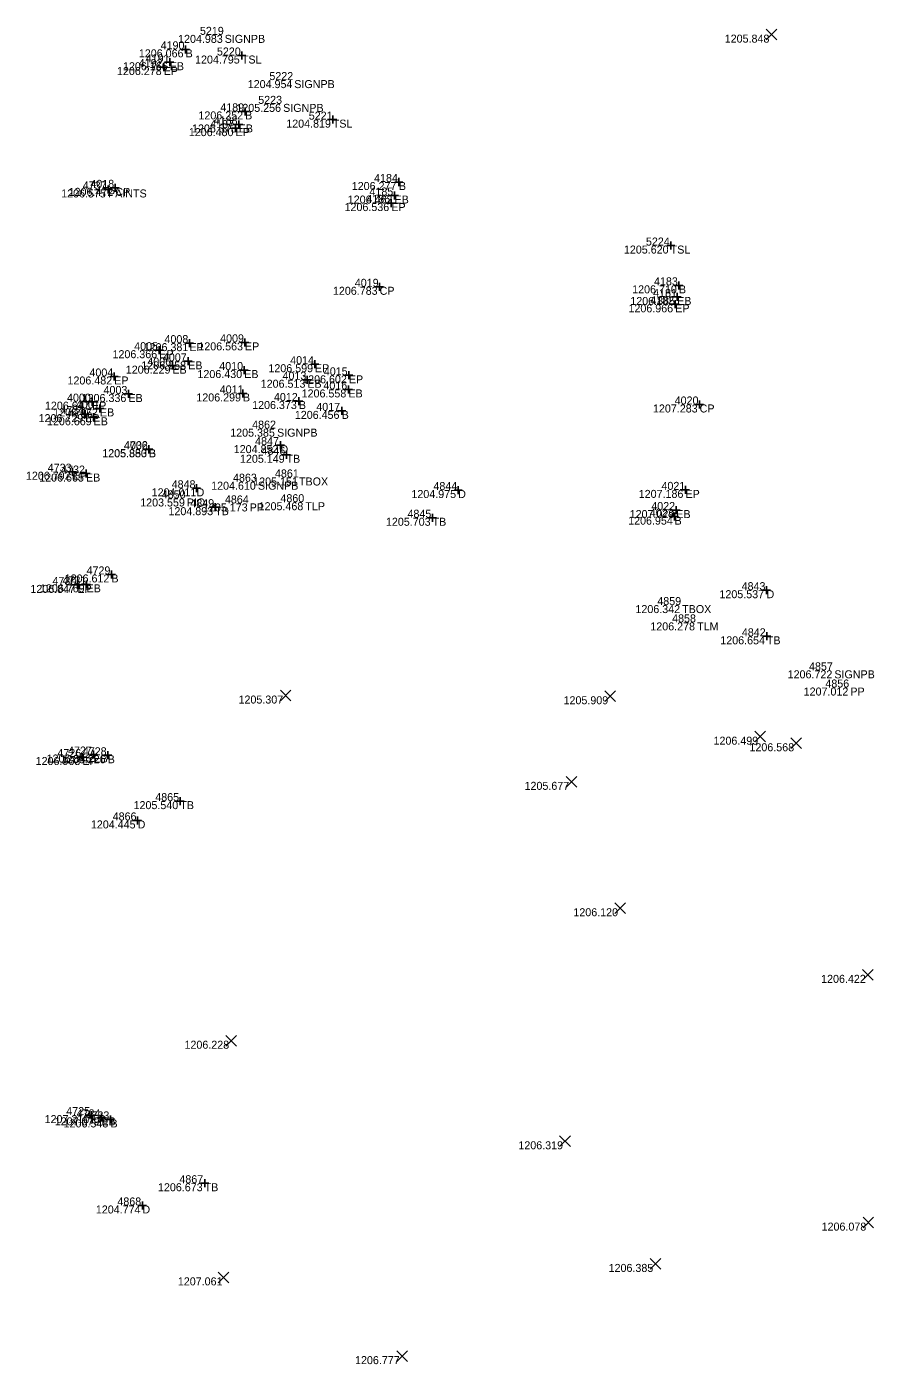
# Model space of a CAD drawing. Extents: x 2044997 to 2050342, y 455233 to 458054.
# Drawn here: x 2047638.8 to 2047744.6, y 456841.8 to 457008.9 of the extents above; entities that cross this region are included whole.
import ezdxf

# ---------------------------------------------------------------- set-up
doc = ezdxf.new("R2010")
doc.units = 0
for name, color, linetype in [('SV_X_Random_Point', 7, 'Continuous'), ('SV_X_Shot_Marker', 7, 'Continuous'), ('SV_X_Text_Comment', 7, 'Continuous'), ('SV_X_Text_Elevation', 7, 'Continuous'), ('SV_X_Text_Name', 7, 'Continuous')]:
    doc.layers.add(name, color=color, linetype=linetype)

msp = doc.modelspace()

# ---------------------------------------------------------------- linework, layer by layer
at = {"layer": 'SV_X_Random_Point'}
for p, q in [((2047731.12, 457007.26), (2047732.46, 457008.6)), ((2047731.12, 457008.6), (2047732.46, 457007.26)), ((2047670.46, 456924.7), (2047671.79, 456926.04)), ((2047670.46, 456926.04), (2047671.79, 456924.7)), ((2047710.98, 456924.61), (2047712.32, 456925.95)), ((2047710.98, 456925.95), (2047712.32, 456924.61)), ((2047729.71, 456919.57), (2047731.04, 456920.9)), ((2047729.71, 456920.9), (2047731.04, 456919.57)), ((2047734.22, 456918.74), (2047735.56, 456920.08)), ((2047734.22, 456920.08), (2047735.56, 456918.74)), ((2047706.17, 456913.92), (2047707.51, 456915.25)), ((2047706.17, 456915.25), (2047707.51, 456913.92)), ((2047712.23, 456898.14), (2047713.56, 456899.47)), ((2047712.23, 456899.47), (2047713.56, 456898.14)), ((2047743.16, 456889.81), (2047744.5, 456891.15)), ((2047743.16, 456891.15), (2047744.5, 456889.81)), ((2047663.66, 456881.58), (2047664.99, 456882.92)), ((2047663.66, 456882.92), (2047664.99, 456881.58)), ((2047705.34, 456869.02), (2047706.68, 456870.35)), ((2047705.34, 456870.35), (2047706.68, 456869.02)), ((2047743.23, 456858.86), (2047744.56, 456860.2)), ((2047743.23, 456860.2), (2047744.56, 456858.86)), ((2047716.64, 456853.71), (2047717.98, 456855.04)), ((2047716.64, 456855.04), (2047717.98, 456853.71)), ((2047662.71, 456852.02), (2047664.04, 456853.36)), ((2047662.71, 456853.36), (2047664.04, 456852.02)), ((2047685, 456842.18), (2047686.33, 456843.52)), ((2047685, 456843.52), (2047686.33, 456842.18))]:
    msp.add_line(p, q, dxfattribs=at)
at = {"layer": 'SV_X_Shot_Marker'}
for p, q in [((2047658.13, 457006.09), (2047659.13, 457006.09)), ((2047658.63, 457006.59), (2047658.63, 457005.59)), ((2047658.63, 457006.09), (2047658.63, 457006.09)), ((2047665.16, 457005.32), (2047666.16, 457005.32)), ((2047665.66, 457005.82), (2047665.66, 457004.82)), ((2047665.66, 457005.32), (2047665.66, 457005.32)), ((2047655.4, 457003.88), (2047656.4, 457003.88)), ((2047655.9, 457004.38), (2047655.9, 457003.38)), ((2047655.9, 457003.88), (2047655.9, 457003.88)), ((2047656.15, 457004.48), (2047657.15, 457004.48)), ((2047656.65, 457004.98), (2047656.65, 457003.98)), ((2047656.65, 457004.48), (2047656.65, 457004.48)), ((2047666.06, 456998.84), (2047666.06, 456997.84)), ((2047665.26, 456997.21), (2047665.26, 456996.21)), ((2047665.56, 456998.34), (2047666.56, 456998.34)), ((2047666.06, 456998.34), (2047666.06, 456998.34)), ((2047676.51, 456997.31), (2047677.51, 456997.31)), ((2047677.01, 456997.81), (2047677.01, 456996.81)), ((2047677.01, 456997.31), (2047677.01, 456997.31)), ((2047664.37, 456996.25), (2047665.37, 456996.25)), ((2047664.76, 456996.71), (2047665.76, 456996.71)), ((2047664.87, 456996.75), (2047664.87, 456995.75)), ((2047664.87, 456996.25), (2047664.87, 456996.25)), ((2047665.26, 456996.71), (2047665.26, 456996.71)), ((2047648.94, 456989.09), (2047648.94, 456988.09)), ((2047649.35, 456988.79), (2047650.35, 456988.79)), ((2047649.85, 456989.29), (2047649.85, 456988.29)), ((2047649.85, 456988.79), (2047649.85, 456988.79)), ((2047684.76, 456989.52), (2047685.76, 456989.52)), ((2047685.26, 456990.02), (2047685.26, 456989.02)), ((2047685.26, 456989.52), (2047685.26, 456989.52)), ((2047648.44, 456988.59), (2047649.44, 456988.59)), ((2047648.94, 456988.59), (2047648.94, 456988.59)), ((2047684.22, 456987.83), (2047685.22, 456987.83)), ((2047684.32, 456987.39), (2047684.32, 456986.39)), ((2047684.72, 456988.33), (2047684.72, 456987.33)), ((2047684.72, 456987.83), (2047684.72, 456987.83)), ((2047683.82, 456986.89), (2047684.82, 456986.89)), ((2047684.32, 456986.89), (2047684.32, 456986.89)), ((2047719.21, 456982.08), (2047719.21, 456981.08)), ((2047718.71, 456981.58), (2047719.71, 456981.58)), ((2047719.21, 456981.58), (2047719.21, 456981.58)), ((2047682.86, 456976.93), (2047682.86, 456975.93)), ((2047720.24, 456977.11), (2047720.24, 456976.11)), ((2047682.36, 456976.43), (2047683.36, 456976.43)), ((2047682.86, 456976.43), (2047682.86, 456976.43)), ((2047719.74, 456976.61), (2047720.74, 456976.61)), ((2047720.02, 456975.66), (2047720.02, 456974.66)), ((2047720.24, 456976.61), (2047720.24, 456976.61)), ((2047719.28, 456974.24), (2047720.28, 456974.24)), ((2047719.52, 456975.16), (2047720.52, 456975.16)), ((2047719.78, 456974.74), (2047719.78, 456973.74)), ((2047719.78, 456974.24), (2047719.78, 456974.24)), ((2047720.02, 456975.16), (2047720.02, 456975.16)), ((2047655.34, 456969.01), (2047655.34, 456968.01)), ((2047658.61, 456969.39), (2047659.61, 456969.39)), ((2047659.11, 456969.89), (2047659.11, 456968.89)), ((2047659.11, 456969.39), (2047659.11, 456969.39)), ((2047665.54, 456969.49), (2047666.54, 456969.49)), ((2047666.04, 456969.99), (2047666.04, 456968.99)), ((2047666.04, 456969.49), (2047666.04, 456969.49)), ((2047654.84, 456968.51), (2047655.84, 456968.51)), ((2047655.34, 456968.51), (2047655.34, 456968.51)), ((2047656.98, 456967.08), (2047656.98, 456966.08)), ((2047658.45, 456967.12), (2047659.45, 456967.12)), ((2047658.95, 456967.62), (2047658.95, 456966.62)), ((2047658.95, 456967.12), (2047658.95, 456967.12)), ((2047674.78, 456967.26), (2047674.78, 456966.26)), ((2047649.21, 456965.23), (2047650.21, 456965.23)), ((2047649.71, 456965.73), (2047649.71, 456964.73)), ((2047649.71, 456965.23), (2047649.71, 456965.23)), ((2047656.48, 456966.58), (2047657.48, 456966.58)), ((2047656.98, 456966.58), (2047656.98, 456966.58)), ((2047665.45, 456966.03), (2047666.45, 456966.03)), ((2047665.95, 456966.53), (2047665.95, 456965.53)), ((2047665.95, 456966.03), (2047665.95, 456966.03)), ((2047673.83, 456965.32), (2047673.83, 456964.32)), ((2047674.28, 456966.76), (2047675.28, 456966.76)), ((2047674.78, 456966.76), (2047674.78, 456966.76)), ((2047678.52, 456965.37), (2047679.52, 456965.37)), ((2047679.02, 456965.87), (2047679.02, 456964.87)), ((2047679.02, 456965.37), (2047679.02, 456965.37)), ((2047665.79, 456963.61), (2047665.79, 456962.61)), ((2047673.33, 456964.82), (2047674.33, 456964.82)), ((2047673.83, 456964.82), (2047673.83, 456964.82)), ((2047678.46, 456963.61), (2047679.46, 456963.61)), ((2047678.96, 456964.11), (2047678.96, 456963.11)), ((2047678.96, 456963.61), (2047678.96, 456963.61)), ((2047646.44, 456962.08), (2047647.44, 456962.08)), ((2047646.94, 456962.58), (2047646.94, 456961.58)), ((2047646.94, 456962.08), (2047646.94, 456962.08)), ((2047650.99, 456963.04), (2047651.99, 456963.04)), ((2047651.49, 456963.54), (2047651.49, 456962.54)), ((2047651.49, 456963.04), (2047651.49, 456963.04)), ((2047665.29, 456963.11), (2047666.29, 456963.11)), ((2047665.79, 456963.11), (2047665.79, 456963.11)), ((2047672.27, 456962.16), (2047673.27, 456962.16)), ((2047672.77, 456962.66), (2047672.77, 456961.66)), ((2047672.77, 456962.16), (2047672.77, 456962.16)), ((2047722.83, 456962.23), (2047722.83, 456961.23)), ((2047645.59, 456960.52), (2047646.59, 456960.52)), ((2047646.09, 456961.02), (2047646.09, 456960.02)), ((2047646.09, 456960.52), (2047646.09, 456960.52)), ((2047647.14, 456960.63), (2047647.14, 456959.63)), ((2047647.43, 456961.24), (2047648.43, 456961.24)), ((2047647.93, 456961.74), (2047647.93, 456960.74)), ((2047647.93, 456961.24), (2047647.93, 456961.24)), ((2047677.62, 456960.93), (2047678.62, 456960.93)), ((2047678.12, 456961.43), (2047678.12, 456960.43)), ((2047678.12, 456960.93), (2047678.12, 456960.93)), ((2047722.33, 456961.73), (2047723.33, 456961.73)), ((2047722.83, 456961.73), (2047722.83, 456961.73)), ((2047646.64, 456960.13), (2047647.64, 456960.13)), ((2047647.14, 456960.13), (2047647.14, 456960.13)), ((2047670.47, 456957.15), (2047670.47, 456956.15)), ((2047653.54, 456956.12), (2047654.54, 456956.12)), ((2047653.55, 456956.15), (2047654.55, 456956.15)), ((2047654.04, 456956.62), (2047654.04, 456955.62)), ((2047654.04, 456956.12), (2047654.04, 456956.12)), ((2047654.05, 456956.65), (2047654.05, 456955.65)), ((2047654.05, 456956.15), (2047654.05, 456956.15)), ((2047669.97, 456956.65), (2047670.97, 456956.65)), ((2047670.47, 456956.65), (2047670.47, 456956.65)), ((2047670.73, 456955.45), (2047671.73, 456955.45)), ((2047671.23, 456955.95), (2047671.23, 456954.95)), ((2047671.23, 456955.45), (2047671.23, 456955.45)), ((2047644.52, 456953.83), (2047644.52, 456952.83)), ((2047646.19, 456953.6), (2047646.19, 456952.6)), ((2047644.02, 456953.33), (2047645.02, 456953.33)), ((2047644.52, 456953.33), (2047644.52, 456953.33)), ((2047645.69, 456953.1), (2047646.69, 456953.1)), ((2047646.19, 456953.1), (2047646.19, 456953.1)), ((2047659.5, 456951.26), (2047660.5, 456951.26)), ((2047660, 456951.76), (2047660, 456950.76)), ((2047660, 456951.26), (2047660, 456951.26)), ((2047692.17, 456951.04), (2047693.17, 456951.04)), ((2047692.67, 456951.54), (2047692.67, 456950.54)), ((2047692.67, 456951.04), (2047692.67, 456951.04)), ((2047720.56, 456951.06), (2047721.56, 456951.06)), ((2047721.06, 456951.56), (2047721.06, 456950.56)), ((2047721.06, 456951.06), (2047721.06, 456951.06)), ((2047661.82, 456948.9), (2047662.82, 456948.9)), ((2047662.32, 456949.4), (2047662.32, 456948.4)), ((2047662.32, 456948.9), (2047662.32, 456948.9)), ((2047719.41, 456948.54), (2047720.41, 456948.54)), ((2047719.91, 456949.04), (2047719.91, 456948.04)), ((2047719.91, 456948.54), (2047719.91, 456948.54)), ((2047688.97, 456947.58), (2047689.97, 456947.58)), ((2047689.47, 456948.08), (2047689.47, 456947.08)), ((2047689.47, 456947.58), (2047689.47, 456947.58)), ((2047719.2, 456947.72), (2047720.2, 456947.72)), ((2047719.7, 456948.22), (2047719.7, 456947.22)), ((2047719.7, 456947.72), (2047719.7, 456947.72)), ((2047648.86, 456940.5), (2047649.86, 456940.5)), ((2047649.36, 456941), (2047649.36, 456940)), ((2047649.36, 456940.5), (2047649.36, 456940.5)), ((2047644.62, 456939.19), (2047645.62, 456939.19)), ((2047645.12, 456939.69), (2047645.12, 456938.69)), ((2047645.12, 456939.19), (2047645.12, 456939.19)), ((2047645.76, 456939.26), (2047646.76, 456939.26)), ((2047646.26, 456939.76), (2047646.26, 456938.76)), ((2047646.26, 456939.26), (2047646.26, 456939.26)), ((2047730.68, 456938.53), (2047731.68, 456938.53)), ((2047731.18, 456939.03), (2047731.18, 456938.03)), ((2047731.18, 456938.53), (2047731.18, 456938.53)), ((2047730.72, 456932.77), (2047731.72, 456932.77)), ((2047731.22, 456933.27), (2047731.22, 456932.27)), ((2047731.22, 456932.77), (2047731.22, 456932.77)), ((2047647.12, 456918.5), (2047647.12, 456917.5)), ((2047645.23, 456917.69), (2047646.23, 456917.69)), ((2047645.73, 456918.19), (2047645.73, 456917.19)), ((2047645.73, 456917.69), (2047645.73, 456917.69)), ((2047646.62, 456918), (2047647.62, 456918)), ((2047647.12, 456918), (2047647.12, 456918)), ((2047648.4, 456917.91), (2047649.4, 456917.91)), ((2047648.9, 456918.41), (2047648.9, 456917.41)), ((2047648.9, 456917.91), (2047648.9, 456917.91)), ((2047657.47, 456912.18), (2047658.47, 456912.18)), ((2047657.97, 456912.68), (2047657.97, 456911.68)), ((2047657.97, 456912.18), (2047657.97, 456912.18)), ((2047652.64, 456910.27), (2047652.64, 456909.27)), ((2047652.14, 456909.77), (2047653.14, 456909.77)), ((2047652.64, 456909.77), (2047652.64, 456909.77)), ((2047646.85, 456873.46), (2047646.85, 456872.46)), ((2047646.35, 456872.96), (2047647.35, 456872.96)), ((2047646.85, 456872.96), (2047646.85, 456872.96)), ((2047647.61, 456872.68), (2047648.61, 456872.68)), ((2047648.11, 456873.18), (2047648.11, 456872.18)), ((2047648.11, 456872.68), (2047648.11, 456872.68)), ((2047648.74, 456872.42), (2047649.74, 456872.42)), ((2047649.24, 456872.92), (2047649.24, 456871.92)), ((2047649.24, 456872.42), (2047649.24, 456872.42)), ((2047660.51, 456864.45), (2047661.51, 456864.45)), ((2047661.01, 456864.95), (2047661.01, 456863.95)), ((2047661.01, 456864.45), (2047661.01, 456864.45)), ((2047652.73, 456861.67), (2047653.73, 456861.67)), ((2047653.23, 456862.17), (2047653.23, 456861.17)), ((2047653.23, 456861.67), (2047653.23, 456861.67))]:
    msp.add_line(p, q, dxfattribs=at)

# ---------------------------------------------------------------- texts
at = {"layer": 'SV_X_Text_Comment'}
for s, p in [('SIGNPB', (2047663.51, 457006.9)), ('B', (2047658.63, 457005.09)), ('TSL', (2047665.66, 457004.32)), ('EP', (2047655.9, 457002.88)), ('EB', (2047656.65, 457003.48)), ('SIGNPB', (2047672.2, 457001.25)), ('SIGNPB', (2047670.81, 456998.28)), ('B', (2047666.06, 456997.34)), ('TSL', (2047677.01, 456996.31)), ('EP', (2047664.87, 456995.25)), ('EB', (2047665.26, 456995.71)), ('CP', (2047649.85, 456987.79)), ('B', (2047685.26, 456988.52)), ('PAINTS', (2047648.94, 456987.59)), ('EB', (2047684.72, 456986.83)), ('EP', (2047684.32, 456985.89)), ('TSL', (2047719.21, 456980.58)), ('CP', (2047682.86, 456975.43)), ('B', (2047720.24, 456975.61)), ('EP', (2047719.78, 456973.24)), ('EB', (2047720.02, 456974.16)), ('EP', (2047659.11, 456968.39)), ('EP', (2047666.04, 456968.49)), ('EP', (2047655.34, 456967.51)), ('EB', (2047658.95, 456966.12)), ('EP', (2047649.71, 456964.23)), ('EB', (2047656.98, 456965.58)), ('EB', (2047665.95, 456965.03)), ('EP', (2047674.78, 456965.76)), ('EP', (2047679.02, 456964.37)), ('EB', (2047673.83, 456963.82)), ('EB', (2047678.96, 456962.61)), ('EP', (2047646.94, 456961.08)), ('EB', (2047651.49, 456962.04)), ('B', (2047665.79, 456962.11)), ('B', (2047672.77, 456961.16)), ('EP', (2047646.09, 456959.52)), ('EB', (2047647.93, 456960.24)), ('B', (2047678.12, 456959.93)), ('CP', (2047722.83, 456960.73)), ('EB', (2047647.14, 456959.13)), ('SIGNPB', (2047670.05, 456957.71)), ('B', (2047654.04, 456955.12)), ('B', (2047654.05, 456955.15)), ('D', (2047670.47, 456955.65)), ('TB', (2047671.23, 456954.45)), ('EP', (2047644.52, 456952.33)), ('EB', (2047646.19, 456952.1)), ('SIGNPB', (2047667.66, 456951.08)), ('TBOX', (2047672.79, 456951.61)), ('D', (2047660, 456950.26)), ('D', (2047692.67, 456950.04)), ('EP', (2047721.06, 456950.06)), ('PIO', (2047658.77, 456948.99)), ('TB', (2047662.32, 456947.9)), ('PP', (2047666.63, 456948.37)), ('TLP', (2047673.59, 456948.52)), ('EB', (2047719.91, 456947.54)), ('TB', (2047689.47, 456946.58)), ('B', (2047719.7, 456946.72)), ('B', (2047649.36, 456939.5)), ('EP', (2047645.12, 456938.19)), ('EB', (2047646.26, 456938.26)), ('D', (2047731.18, 456937.53)), ('TBOX', (2047720.64, 456935.67)), ('TLM', (2047722.51, 456933.51)), ('TB', (2047731.22, 456931.77)), ('SIGNPB', (2047739.65, 456927.52)), ('PP', (2047741.65, 456925.37)), ('EP', (2047645.73, 456916.69)), ('EB', (2047647.12, 456917)), ('B', (2047648.9, 456916.91)), ('TB', (2047657.97, 456911.18)), ('D', (2047652.64, 456908.77)), ('EP', (2047646.85, 456871.96)), ('EB', (2047648.11, 456871.68)), ('B', (2047649.24, 456871.42)), ('TB', (2047661.01, 456863.45)), ('D', (2047653.23, 456860.67))]:
    msp.add_text(s, height=1, dxfattribs=at).set_placement(p)
at = {"layer": 'SV_X_Text_Elevation'}
for s, p in [('1204.983', (2047657.69, 457006.9)), ('1205.848', (2047725.96, 457006.93)), ('1206.066', (2047652.79, 457005.09)), ('1204.795', (2047659.81, 457004.32)), ('1206.278', (2047650.06, 457002.88)), ('1206.166', (2047650.81, 457003.48)), ('1204.954', (2047666.39, 457001.25)), ('1205.256', (2047664.97, 456998.28)), ('1206.252', (2047660.23, 456997.34)), ('1204.819', (2047671.2, 456996.31)), ('1206.480', (2047659.03, 456995.25)), ('1206.373', (2047659.43, 456995.71)), ('1206.472', (2047644.02, 456987.79)), ('1206.277', (2047679.38, 456988.52)), ('1206.575', (2047643.09, 456987.59)), ('1206.462', (2047678.88, 456986.83)), ('1206.536', (2047678.48, 456985.89)), ('1205.620', (2047713.37, 456980.58)), ('1206.783', (2047677.03, 456975.43)), ('1206.710', (2047714.4, 456975.61)), ('1206.966', (2047713.94, 456973.24)), ('1206.885', (2047714.17, 456974.16)), ('1206.381', (2047653.39, 456968.39)), ('1206.563', (2047660.22, 456968.49)), ('1206.366', (2047649.5, 456967.51)), ('1206.258', (2047653.11, 456966.12)), ('1206.482', (2047643.88, 456964.23)), ('1206.229', (2047651.16, 456965.58)), ('1206.430', (2047660.11, 456965.03)), ('1206.599', (2047668.97, 456965.76)), ('1206.602', (2047673.19, 456964.37)), ('1206.513', (2047668.01, 456963.82)), ('1206.558', (2047673.12, 456962.61)), ('1206.647', (2047641.06, 456961.08)), ('1206.336', (2047645.65, 456962.04)), ('1206.299', (2047659.97, 456962.11)), ('1206.373', (2047666.94, 456961.16)), ('1206.729', (2047640.27, 456959.52)), ('1206.472', (2047642.09, 456960.24)), ('1206.456', (2047672.27, 456959.93)), ('1207.283', (2047717, 456960.73)), ('1206.669', (2047641.32, 456959.13)), ('1205.385', (2047664.2, 456957.71)), ('1205.880', (2047648.21, 456955.12)), ('1205.853', (2047648.23, 456955.15)), ('1204.852', (2047664.64, 456955.65)), ('1205.149', (2047665.42, 456954.45)), ('1206.792', (2047638.69, 456952.33)), ('1206.665', (2047640.35, 456952.1)), ('1204.610', (2047661.82, 456951.08)), ('1205.151', (2047667.07, 456951.61)), ('1204.011', (2047654.39, 456950.26)), ('1204.975', (2047686.83, 456950.04)), ('1207.186', (2047715.22, 456950.06)), ('1203.559', (2047652.96, 456948.99)), ('1204.893', (2047656.49, 456947.9)), ('1205.173', (2047660.8, 456948.37)), ('1205.468', (2047667.75, 456948.52)), ('1207.029', (2047714.09, 456947.54)), ('1205.703', (2047683.65, 456946.58)), ('1206.954', (2047713.9, 456946.72)), ('1206.612', (2047643.53, 456939.5)), ('1206.847', (2047639.24, 456938.19)), ('1206.769', (2047640.44, 456938.26)), ('1205.537', (2047725.3, 456937.53)), ('1206.342', (2047714.81, 456935.67)), ('1206.278', (2047716.67, 456933.51)), ('1206.654', (2047725.41, 456931.77)), ('1206.722', (2047733.82, 456927.52)), ('1205.307', (2047665.24, 456924.37)), ('1205.909', (2047705.83, 456924.28)), ('1207.012', (2047735.82, 456925.37)), ('1206.499', (2047724.56, 456919.23)), ('1206.568', (2047729.05, 456918.41)), ('1206.963', (2047639.9, 456916.69)), ('1206.846', (2047641.27, 456917)), ('1206.226', (2047643.06, 456916.91)), ('1205.677', (2047700.96, 456913.59)), ('1205.540', (2047652.13, 456911.18)), ('1204.445', (2047646.8, 456908.77)), ('1206.120', (2047707.06, 456897.8)), ('1206.422', (2047738, 456889.48)), ('1206.228', (2047658.49, 456881.25)), ('1207.210', (2047641.02, 456871.96)), ('1207.079', (2047642.29, 456871.68)), ('1206.548', (2047643.4, 456871.42)), ('1206.319', (2047700.19, 456868.69)), ('1206.673', (2047655.18, 456863.45)), ('1204.774', (2047647.42, 456860.67)), ('1206.078', (2047738.06, 456858.53)), ('1206.385', (2047711.46, 456853.37)), ('1207.061', (2047657.66, 456851.69)), ('1206.777', (2047679.79, 456841.85))]:
    msp.add_text(s, height=1, dxfattribs=at).set_placement(p)
at = {"layer": 'SV_X_Text_Name'}
for s, p in [('5219', (2047660.42, 457007.9)), ('4190', (2047655.51, 457006.09)), ('4191', (2047653.65, 457004.48)), ('5220', (2047662.54, 457005.32)), ('4192', (2047652.78, 457003.88)), ('5222', (2047669.09, 457002.25)), ('4189', (2047662.96, 456998.34)), ('5223', (2047667.7, 456999.28)), ('4187', (2047661.7, 456996.25)), ('4188', (2047662.14, 456996.71)), ('5221', (2047674.01, 456997.31)), ('4184', (2047682.17, 456989.52)), ('4737', (2047645.78, 456988.59)), ('4018', (2047646.73, 456988.79)), ('4185', (2047681.59, 456987.83)), ('4186', (2047681.2, 456986.89)), ('5224', (2047716.12, 456981.58)), ('4019', (2047679.76, 456976.43)), ('4183', (2047717.13, 456976.61)), ('4182', (2047716.66, 456974.24)), ('4181', (2047717.02, 456975.16)), ('4008', (2047655.99, 456969.39)), ('4009', (2047662.94, 456969.49)), ('4005', (2047652.21, 456968.51)), ('4006', (2047653.85, 456966.58)), ('4007', (2047655.79, 456967.12)), ('4010', (2047662.83, 456966.03)), ('4014', (2047671.69, 456966.76)), ('4004', (2047646.62, 456965.23)), ('4013', (2047670.73, 456964.82)), ('4015', (2047675.89, 456965.37)), ('4003', (2047648.38, 456963.04)), ('4011', (2047662.89, 456963.11)), ('4016', (2047675.84, 456963.61)), ('4000', (2047643.82, 456962.08)), ('4001', (2047644.93, 456961.24)), ('4012', (2047669.66, 456962.16)), ('4017', (2047674.95, 456960.93)), ('4020', (2047719.71, 456961.73)), ('4734', (2047643, 456960.52)), ('4735', (2047644.01, 456960.13)), ('4862', (2047666.94, 456958.71)), ('4736', (2047650.92, 456956.12)), ('4002', (2047650.94, 456956.15)), ('4847', (2047667.31, 456956.65)), ('4846', (2047668.11, 456955.45)), ('4733', (2047641.41, 456953.33)), ('4732', (2047643.08, 456953.1)), ('4861', (2047669.79, 456952.61)), ('4848', (2047656.89, 456951.26)), ('4863', (2047664.55, 456952.08)), ('4844', (2047689.58, 456951.04)), ('4021', (2047718.06, 456951.06)), ('4850', (2047655.65, 456949.99)), ('4864', (2047663.54, 456949.37)), ('4860', (2047670.47, 456949.52)), ('4849', (2047659.22, 456948.9)), ('4845', (2047686.34, 456947.58)), ('4023', (2047716.6, 456947.72)), ('4022', (2047716.79, 456948.54)), ('4730', (2047642, 456939.19)), ('4731', (2047643.26, 456939.26)), ('4729', (2047646.26, 456940.5)), ('4843', (2047728.07, 456938.53)), ('4859', (2047717.54, 456936.67)), ('4858', (2047719.39, 456934.51)), ('4842', (2047728.1, 456932.77)), ('4857', (2047736.49, 456928.52)), ('4856', (2047738.53, 456926.37)), ('4726', (2047642.61, 456917.69)), ('4727', (2047643.95, 456918)), ('4728', (2047645.79, 456917.91)), ('4865', (2047654.84, 456912.18)), ('4866', (2047649.52, 456909.77)), ('4725', (2047643.72, 456872.96)), ('4724', (2047645.02, 456872.68)), ('4723', (2047646.13, 456872.42)), ('4867', (2047657.85, 456864.45)), ('4868', (2047650.11, 456861.67))]:
    msp.add_text(s, height=1, dxfattribs=at).set_placement(p)

doc.saveas('drawing.dxf')
